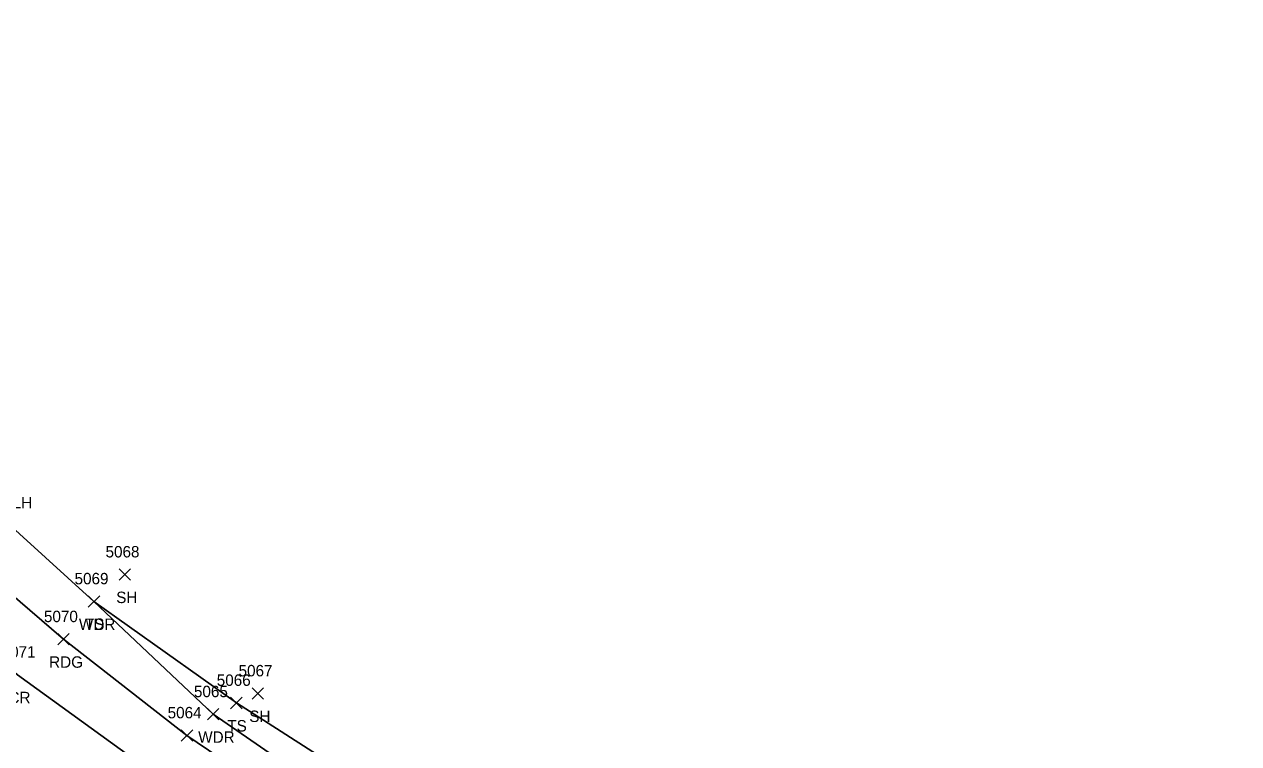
# Model space of a CAD drawing. Extents: x 1653135 to 1655489, y 602711 to 605684.
# Drawn here: x 1653472.7 to 1653685.6, y 605377.9 to 605504 of the extents above; entities that cross this region are included whole.
import ezdxf

# ---------------------------------------------------------------- set-up
doc = ezdxf.new("R2010")
doc.units = 0
for name, color, linetype in [('D_A', 7, 'Continuous'), ('L_A', 7, 'Continuous'), ('L_I', 7, 'Continuous'), ('L_TIC', 7, 'Continuous'), ('LAWA', 7, 'Continuous'), ('LELB', 7, 'Continuous'), ('P_A', 7, 'Continuous'), ('P_I', 7, 'Continuous'), ('P_TIC', 7, 'Continuous'), ('PEU', 7, 'Continuous'), ('PRC', 7, 'Continuous')]:
    doc.layers.add(name, color=color, linetype=linetype)

msp = doc.modelspace()

# ---------------------------------------------------------------- linework, layer by layer
at = {"layer": 'L_TIC'}
for points in [[(1653489.31, 605406.55), (1653491.31, 605408.55)], [(1653491.31, 605406.55), (1653489.31, 605408.55)], [(1653489.31, 605406.55), (1653491.31, 605408.55)], [(1653491.31, 605406.55), (1653489.31, 605408.55)], [(1653483.9, 605401.84), (1653485.9, 605403.84)], [(1653485.9, 605401.84), (1653483.9, 605403.84)], [(1653483.9, 605401.84), (1653485.9, 605403.84)], [(1653485.9, 605401.84), (1653483.9, 605403.84)], [(1653483.9, 605401.84), (1653485.9, 605403.84)], [(1653485.9, 605401.84), (1653483.9, 605403.84)], [(1653483.9, 605401.84), (1653485.9, 605403.84)], [(1653485.9, 605401.84), (1653483.9, 605403.84)], [(1653508.87, 605384.03), (1653510.87, 605386.03)], [(1653510.87, 605384.03), (1653508.87, 605386.03)], [(1653508.87, 605384.03), (1653510.87, 605386.03)], [(1653510.87, 605384.03), (1653508.87, 605386.03)], [(1653512.64, 605385.7), (1653514.64, 605387.7)], [(1653514.64, 605385.7), (1653512.64, 605387.7)], [(1653512.64, 605385.7), (1653514.64, 605387.7)], [(1653514.64, 605385.7), (1653512.64, 605387.7)], [(1653504.82, 605382.05), (1653506.82, 605384.05)], [(1653506.82, 605382.05), (1653504.82, 605384.05)], [(1653504.82, 605382.05), (1653506.82, 605384.05)], [(1653506.82, 605382.05), (1653504.82, 605384.05)]]:
    msp.add_lwpolyline(points, dxfattribs=at)
at = {"layer": 'LAWA'}
msp.add_lwpolyline([(1653685.62, 605322.04), (1653670.88, 605332.32), (1653661.72, 605337.52), (1653630.34, 605321.68), (1653616.8, 605320.72), (1653598.43, 605325.95), (1653564.06, 605344.01), (1653534.85, 605363.01), (1653505.82, 605383.05), (1653484.9, 605402.84), (1653463.33, 605422.4), (1653441.69, 605442.64), (1653418.02, 605465.09), (1653400.64, 605492.12), (1653388.1, 605504.01)], dxfattribs=at)
at = {"layer": 'LELB'}
msp.add_lwpolyline([(1653540.6, 605365.35), (1653509.87, 605385.03), (1653484.9, 605402.84)], dxfattribs=at)
at = {"layer": 'P_TIC'}
for points in [[(1653478.55, 605395.21), (1653480.55, 605397.21)], [(1653480.55, 605395.21), (1653478.55, 605397.21)], [(1653478.55, 605395.21), (1653480.55, 605397.21)], [(1653480.55, 605395.21), (1653478.55, 605397.21)], [(1653500.21, 605378.34), (1653502.21, 605380.34)], [(1653502.21, 605378.34), (1653500.21, 605380.34)], [(1653500.21, 605378.34), (1653502.21, 605380.34)], [(1653502.21, 605378.34), (1653500.21, 605380.34)]]:
    msp.add_lwpolyline(points, dxfattribs=at)
at = {"layer": 'PEU'}
msp.add_lwpolyline([(1653653.23, 605280.28), (1653630.46, 605291.02), (1653590.02, 605315.2), (1653557.58, 605338.73), (1653531.08, 605359.13), (1653501.21, 605379.34), (1653479.55, 605396.21), (1653456.3, 605416.21), (1653435.84, 605435.12), (1653411.96, 605460.89), (1653393.13, 605484.25), (1653380.18, 605499.71)], dxfattribs=at)
at = {"layer": 'PRC'}
msp.add_lwpolyline([(1653641.51, 605268.82), (1653619.74, 605284.48), (1653584.5, 605306.53), (1653550.68, 605330.05), (1653524.48, 605350.56), (1653495.62, 605372.52), (1653471.48, 605389.99), (1653448.45, 605410.05), (1653429.44, 605426.79), (1653403.79, 605455.33), (1653385.16, 605477.75), (1653370.74, 605494.28)], dxfattribs=at)

# ---------------------------------------------------------------- texts
at = {"layer": 'D_A'}
msp.add_text('WALLH', height=2, dxfattribs=at).set_placement((1653464.85, 605419.14))
msp.add_text('WALLH', height=2, dxfattribs=at).set_placement((1653464.85, 605419.14))
at = {"layer": 'L_A'}
for s, p in [('SH', (1653488.8, 605402.55)), ('SH', (1653488.8, 605402.55)), ('WDR', (1653482.26, 605397.84)), ('WDR', (1653482.26, 605397.84)), ('TS', (1653483.31, 605397.84)), ('TS', (1653483.31, 605397.84)), ('SH', (1653512.13, 605381.7)), ('SH', (1653512.13, 605381.7)), ('TS', (1653508.28, 605380.03)), ('TS', (1653508.28, 605380.03)), ('WDR', (1653503.18, 605378.05)), ('WDR', (1653503.18, 605378.05))]:
    msp.add_text(s, height=2, dxfattribs=at).set_placement(p)
at = {"layer": 'L_I'}
for s, p in [('5068', (1653486.93, 605410.55)), ('5068', (1653486.93, 605410.55)), ('5069', (1653481.5, 605405.84)), ('5069', (1653481.5, 605405.84)), ('5069', (1653481.5, 605405.84)), ('5069', (1653481.5, 605405.84)), ('5067', (1653510.26, 605389.7)), ('5067', (1653510.26, 605389.7)), ('5065', (1653502.43, 605386.05)), ('5065', (1653502.43, 605386.05)), ('5066', (1653506.43, 605388.03)), ('5066', (1653506.43, 605388.03))]:
    msp.add_text(s, height=2, dxfattribs=at).set_placement(p)
at = {"layer": 'P_A'}
for s, p in [('RDG', (1653477.04, 605391.21)), ('RDG', (1653477.04, 605391.21)), ('CR', (1653469.91, 605384.99)), ('CR', (1653469.91, 605384.99))]:
    msp.add_text(s, height=2, dxfattribs=at).set_placement(p)
at = {"layer": 'P_I'}
for s, p in [('5070', (1653476.13, 605399.21)), ('5070', (1653476.13, 605399.21)), ('5071', (1653468.71, 605392.99)), ('5071', (1653468.71, 605392.99)), ('5064', (1653497.82, 605382.34)), ('5064', (1653497.82, 605382.34))]:
    msp.add_text(s, height=2, dxfattribs=at).set_placement(p)

doc.saveas('drawing.dxf')
